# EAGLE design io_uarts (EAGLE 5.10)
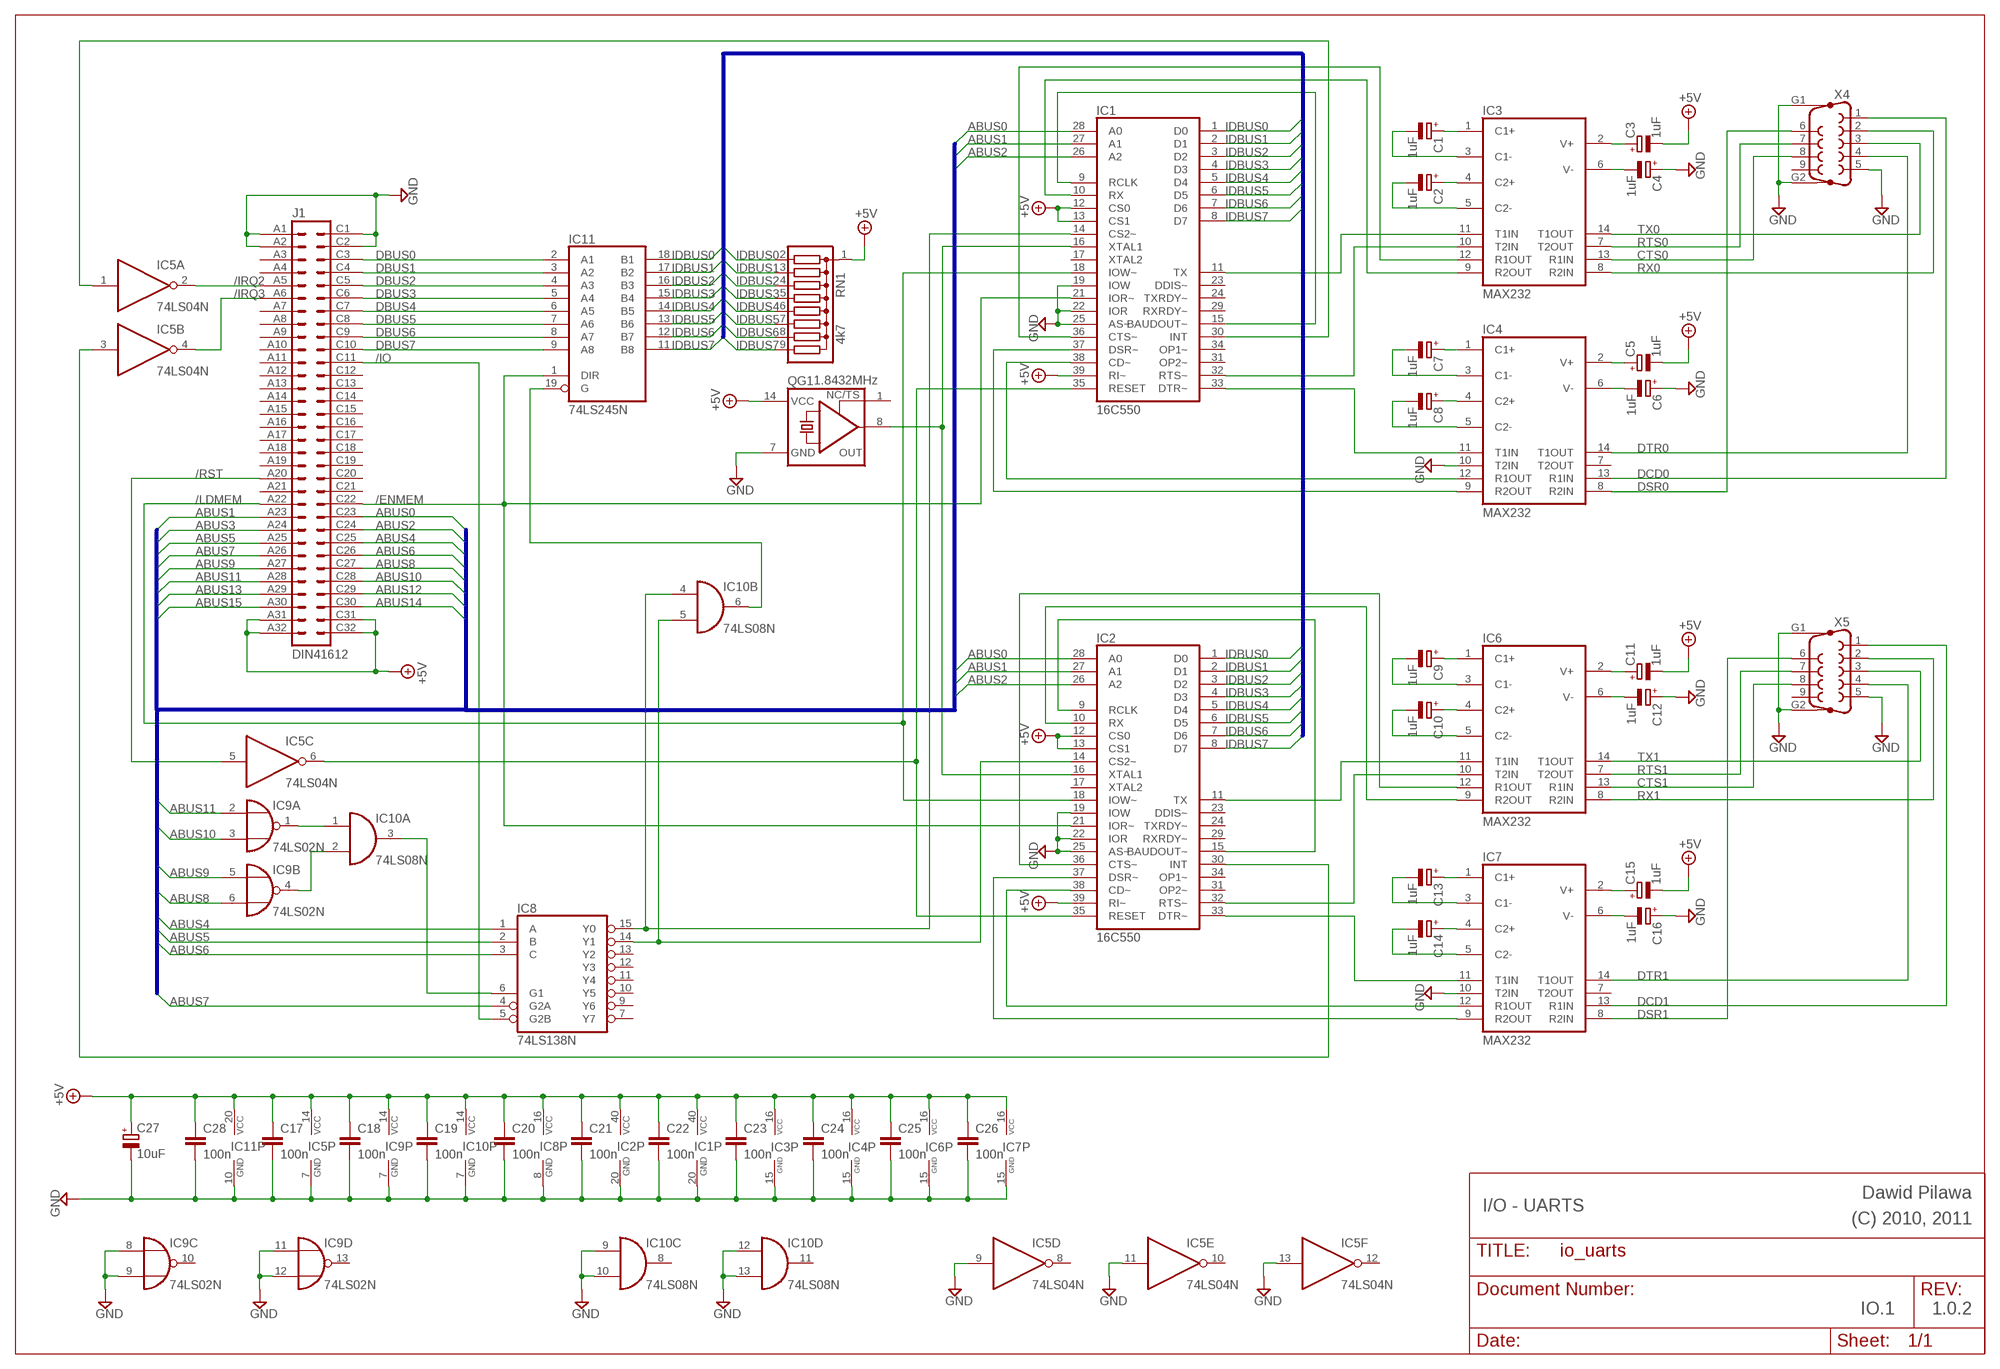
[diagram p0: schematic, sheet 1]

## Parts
C1  1uF  CPOL-EUE5-5  [E5-5]
C2  1uF  CPOL-EUE5-5  [E5-5]
C3  1uF  CPOL-EUE5-5  [E5-5]
C4  1uF  CPOL-EUE5-5  [E5-5]
C5  1uF  CPOL-EUE5-5  [E5-5]
C6  1uF  CPOL-EUE5-5  [E5-5]
C7  1uF  CPOL-EUE5-5  [E5-5]
C8  1uF  CPOL-EUE5-5  [E5-5]
C9  1uF  CPOL-EUE5-5  [E5-5]
C10  1uF  CPOL-EUE5-5  [E5-5]
C11  1uF  CPOL-EUE5-5  [E5-5]
C12  1uF  CPOL-EUE5-5  [E5-5]
C13  1uF  CPOL-EUE5-5  [E5-5]
C14  1uF  CPOL-EUE5-5  [E5-5]
C15  1uF  CPOL-EUE5-5  [E5-5]
C16  1uF  CPOL-EUE5-5  [E5-5]
C17  100n  C-EU050-024X044  [C050-024X044]
C18  100n  C-EU050-024X044  [C050-024X044]
C19  100n  C-EU050-024X044  [C050-024X044]
C20  100n  C-EU050-024X044  [C050-024X044]
C21  100n  C-EU050-024X044  [C050-024X044]
C22  100n  C-EU050-024X044  [C050-024X044]
C23  100n  C-EU050-024X044  [C050-024X044]
C24  100n  C-EU050-024X044  [C050-024X044]
C25  100n  C-EU050-024X044  [C050-024X044]
C26  100n  C-EU050-024X044  [C050-024X044]
C27  10uF  CPOL-EUE5-5  [E5-5]
C28  100n  C-EU050-024X044  [C050-024X044]
IC1  16C550  XR-16C550P  [DIL40]
IC2  16C550  XR-16C550P  [DIL40]
IC3  MAX232  [DIL16]
IC4  MAX232  [DIL16]
IC5  74LS04N  [DIL14]
IC6  MAX232  [DIL16]
IC7  MAX232  [DIL16]
IC8  74LS138N  [DIL16]
IC9  74LS02N  [DIL14]
IC10  74LS08N  [DIL14]
IC11  74LS245N  [DIL20]
J1  DIN41612  VG64B  [VG64B]
QG1  1.8432MHz  XO-14  [DIL14S]
RN1  4k7  G08R  [SIL9]
X4  F09HP  [F09HP]
X5  F09HP  [F09HP]

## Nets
+5V: C3.- C5.- C11.- C15.- C17.1 C18.1 C19.1 C20.1 C21.1 C22.1 C23.1 C24.1 C25.1 C26.1 C27.+ C28.1 IC1.12(CS0) IC1.13(CS1) IC1.39(RI~) IC1.40(VCC) IC2.12(CS0) IC2.13(CS1) IC2.39(RI~) IC2.40(VCC) IC3.16(VCC) IC4.16(VCC) IC5.14(P:VCC) IC6.16(VCC) IC7.16(VCC) IC8.16(VCC) IC9.14(P:VCC) IC10.14(P:VCC) IC11.20(VCC) J1.A31 J1.A32 J1.C31 J1.C32 QG1.14(VCC) RN1.1
/ENMEM: IC1.21(IOR~) IC2.21(IOR~) IC11.1(DIR) J1.C22
/IO: IC8.5(G2B) J1.C11
/IRQ2: IC5.2(A:O) J1.A5
/IRQ3: IC5.4(B:O) J1.A6
/LDMEM: IC1.18(IOW~) IC2.18(IOW~) J1.A22
/RST: IC5.5(C:I) J1.A20
ABUS0: IC1.28(A0) IC2.28(A0) J1.C23
ABUS1: IC1.27(A1) IC2.27(A1) J1.A23
ABUS2: IC1.26(A2) IC2.26(A2) J1.C24
ABUS3: J1.A24
ABUS4: IC8.1(A) J1.C25
ABUS5: IC8.2(B) J1.A25
ABUS6: IC8.3(C) J1.C26
ABUS7: IC8.4(G2A) J1.A26
ABUS8: IC9.6(B:I1) J1.C27
ABUS9: IC9.5(B:I0) J1.A27
ABUS10: IC9.3(A:I1) J1.C28
ABUS11: IC9.2(A:I0) J1.A28
ABUS12: J1.C29
ABUS13: J1.A29
ABUS14: J1.C30
ABUS15: J1.A30
CTS0: IC3.13(R1IN) X4.8
CTS1: IC6.13(R1IN) X5.8
DBUS0: IC11.2(A1) J1.C3
DBUS1: IC11.3(A2) J1.C4
DBUS2: IC11.4(A3) J1.C5
DBUS3: IC11.5(A4) J1.C6
DBUS4: IC11.6(A5) J1.C7
DBUS5: IC11.7(A6) J1.C8
DBUS6: IC11.8(A7) J1.C9
DBUS7: IC11.9(A8) J1.C10
DCD0: IC4.13(R1IN) X4.1
DCD1: IC7.13(R1IN) X5.1
DSR0: IC4.8(R2IN) X4.6
DSR1: IC7.8(R2IN) X5.6
DTR0: IC4.14(T1OUT) X4.4
DTR1: IC7.14(T1OUT) X5.4
GND: C4.+ C6.+ C12.+ C16.+ C17.2 C18.2 C19.2 C20.2 C21.2 C22.2 C23.2 C24.2 C25.2 C26.2 C27.- C28.2 IC1.19(IOW) IC1.20(GND) IC1.22(IOR) IC1.25(AS~) IC2.19(IOW) IC2.20(GND) IC2.22(IOR) IC2.25(AS~) IC3.15(GND) IC4.10(T2IN) IC4.15(GND) IC5.7(P:GND) IC5.9(D:I) IC5.11(E:I) IC5.13(F:I) IC6.15(GND) IC7.10(T2IN) IC7.15(GND) IC8.8(GND) IC9.7(P:GND) IC9.8(C:I0) IC9.9(C:I1) IC9.11(D:I0) IC9.12(D:I1) IC10.7(P:GND) IC10.9(C:I0) IC10.10(C:I1) IC10.12(D:I0) IC10.13(D:I1) IC11.10(GND) J1.A1 J1.A2 J1.C1 J1.C2 QG1.7(GND) X4.5 X4.G1 X4.G2 X5.5 X5.G1 X5.G2
IDBUS0: IC1.1(D0) IC2.1(D0) IC11.18(B1) RN1.2
IDBUS1: IC1.2(D1) IC2.2(D1) IC11.17(B2) RN1.3
IDBUS2: IC1.3(D2) IC2.3(D2) IC11.16(B3) RN1.4
IDBUS3: IC1.4(D3) IC2.4(D3) IC11.15(B4) RN1.5
IDBUS4: IC1.5(D4) IC2.5(D4) IC11.14(B5) RN1.6
IDBUS5: IC1.6(D5) IC2.6(D5) IC11.13(B6) RN1.7
IDBUS6: IC1.7(D6) IC2.7(D6) IC11.12(B7) RN1.8
IDBUS7: IC1.8(D7) IC2.8(D7) IC11.11(B8) RN1.9
N$1: IC1.11(TX) IC3.11(T1IN)
N$2: IC1.10(RX) IC3.9(R2OUT)
N$3: IC10.6(B:O) IC11.19(G)
N$4: IC1.32(RTS~) IC3.10(T2IN)
N$5: IC1.33(DTR~) IC4.11(T1IN)
N$6: IC1.36(CTS~) IC3.12(R1OUT)
N$7: IC1.38(CD~) IC4.12(R1OUT)
N$8: IC1.37(DSR~) IC4.9(R2OUT)
N$9: C1.- IC3.3(C1-)
N$10: C1.+ IC3.1(C1+)
N$11: C2.+ IC3.4(C2+)
N$12: C2.- IC3.5(C2-)
N$13: C4.- IC3.6(V-)
N$14: C3.+ IC3.2(V+)
N$15: IC1.9(RCLK) IC1.15(BAUDOUT~)
N$16: C6.- IC4.6(V-)
N$17: C5.+ IC4.2(V+)
N$18: C7.- IC4.3(C1-)
N$19: C7.+ IC4.1(C1+)
N$20: C8.+ IC4.4(C2+)
N$21: C8.- IC4.5(C2-)
N$22: IC9.1(A:O) IC10.1(A:I0)
N$23: C9.- IC6.3(C1-)
N$24: IC1.30(INT) IC5.1(A:I)
N$25: IC2.30(INT) IC5.3(B:I)
N$26: IC9.4(B:O) IC10.2(A:I1)
N$27: IC8.6(G1) IC10.3(A:O)
N$28: IC1.14(CS2~) IC8.15(Y0) IC10.4(B:I0)
N$29: IC2.14(CS2~) IC8.14(Y1) IC10.5(B:I1)
N$30: IC2.9(RCLK) IC2.15(BAUDOUT~)
N$31: IC2.11(TX) IC6.11(T1IN)
N$32: IC2.32(RTS~) IC6.10(T2IN)
N$33: IC2.33(DTR~) IC7.11(T1IN)
N$34: IC2.38(CD~) IC7.12(R1OUT)
N$35: IC2.37(DSR~) IC7.9(R2OUT)
N$36: IC2.10(RX) IC6.9(R2OUT)
N$37: IC2.36(CTS~) IC6.12(R1OUT)
N$38: C9.+ IC6.1(C1+)
N$39: IC1.35(RESET) IC2.35(RESET) IC5.6(C:O)
N$40: C10.+ IC6.4(C2+)
N$41: C10.- IC6.5(C2-)
N$42: C12.- IC6.6(V-)
N$43: C11.+ IC6.2(V+)
N$44: C13.- IC7.3(C1-)
N$45: C13.+ IC7.1(C1+)
N$46: C14.+ IC7.4(C2+)
N$47: C14.- IC7.5(C2-)
N$48: C16.- IC7.6(V-)
N$49: C15.+ IC7.2(V+)
N$50: IC1.16(XTAL1) IC2.16(XTAL1) QG1.8(OUT)
RTS0: IC3.7(T2OUT) X4.7
RTS1: IC6.7(T2OUT) X5.7
RX0: IC3.8(R2IN) X4.2
RX1: IC6.8(R2IN) X5.2
TX0: IC3.14(T1OUT) X4.3
TX1: IC6.14(T1OUT) X5.3
Unconnected: IC1.17(XTAL2) IC1.23(DDIS~) IC1.24(TXRDY~) IC1.29(RXRDY~) IC1.31(OP2~) IC1.34(OP1~) IC2.17(XTAL2) IC2.23(DDIS~) IC2.24(TXRDY~) IC2.29(RXRDY~) IC2.31(OP2~) IC2.34(OP1~) IC4.7(T2OUT) IC5.8(D:O) IC5.10(E:O) IC5.12(F:O) IC7.7(T2OUT) IC8.7(Y7) IC8.9(Y6) IC8.10(Y5) IC8.11(Y4) IC8.12(Y3) IC8.13(Y2) IC9.10(C:O) IC9.13(D:O) IC10.8(C:O) IC10.11(D:O) J1.A3 J1.A4 J1.A7 J1.A8 J1.A9 J1.A10 J1.A11 J1.A12 J1.A13 J1.A14 J1.A15 J1.A16 J1.A17 J1.A18 J1.A19 J1.A21 J1.C12 J1.C13 J1.C14 J1.C15 J1.C16 J1.C17 J1.C18 J1.C19 J1.C20 J1.C21 QG1.1(TS) X4.9 X5.9

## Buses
ABUS[0..15]
IDBUS[0..7]

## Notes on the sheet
- Dawid Pilawa
- I/O - UARTS | (C) 2010, 2011
- IO.1 | 1.0.2

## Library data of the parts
C1-C16 C27 = rcl:CPOL-EU: POLARIZED CAPACITOR, European symbol
C17-C26 C28 = rcl:C-EU: CAPACITOR, European symbol
IC1 IC2 = exar:XR-16C550P: UART/FIFO
IC3 IC4 IC6 IC7 = maxim:MAX232: RS232 TRANSEIVER
IC5 = 74xx-eu:74*04: Hex INVERTER
IC8 = 74xx-eu:74*138: 3-line to 8-line DECODER/DEMULTIPLEXER
IC9 = 74xx-eu:74*02: Quad 2-input NOR gate
IC10 = 74xx-eu:74*08: Quad 2-input AND gate
IC11 = 74xx-eu:74*245: Octal BUS TRANSCEIVER, 3-state
J1 = 19inch:VG64: PCB EUROCARD, 64-pin type C/AC, 2.54 mm
QG1 = crystal:XO-: CRYSTAL
RN1 = resistor-sil:G08R: SIL RESISTOR
X4 X5 = con-subd:F09HP: SUB-D

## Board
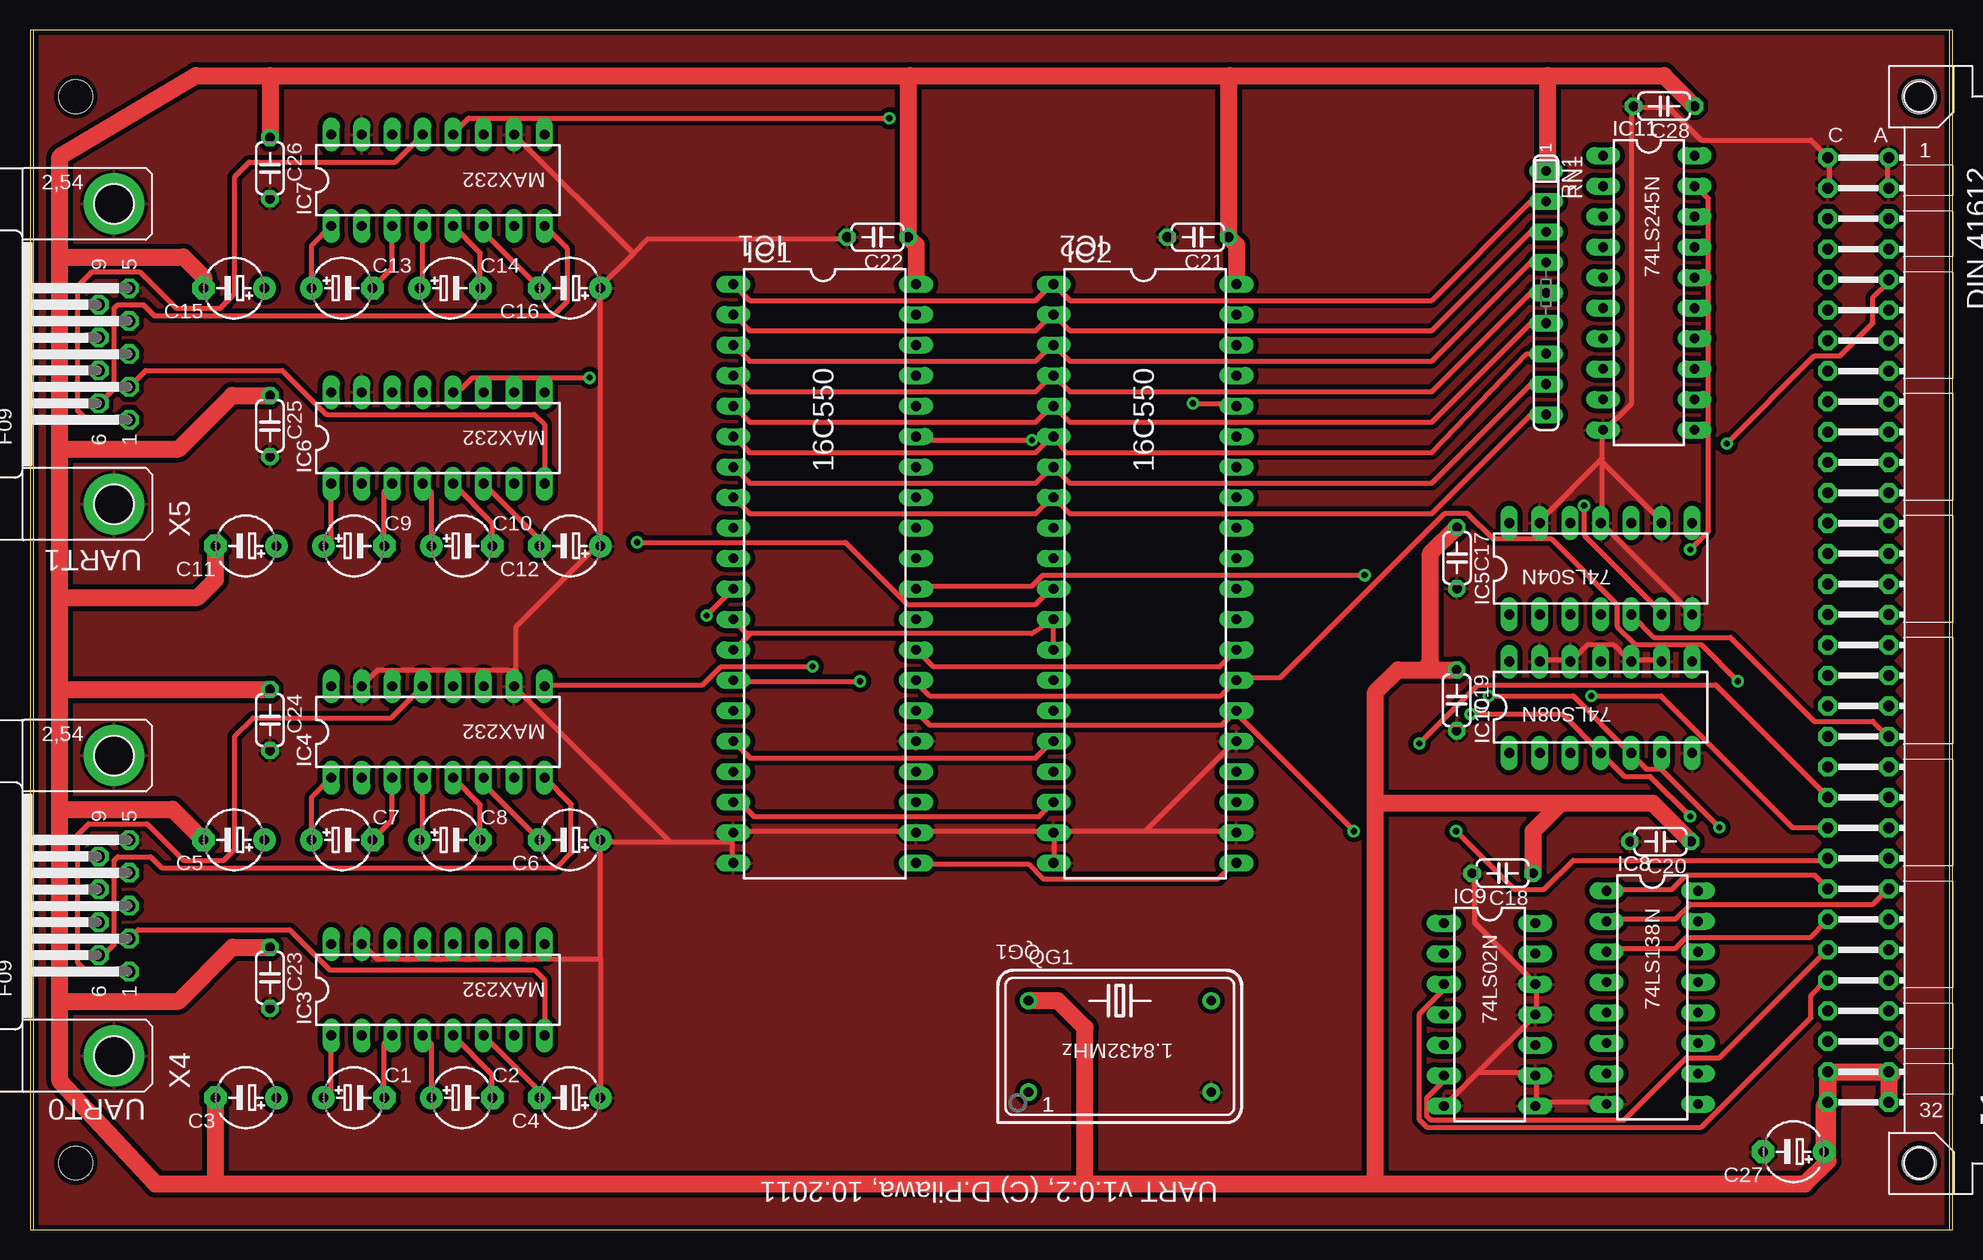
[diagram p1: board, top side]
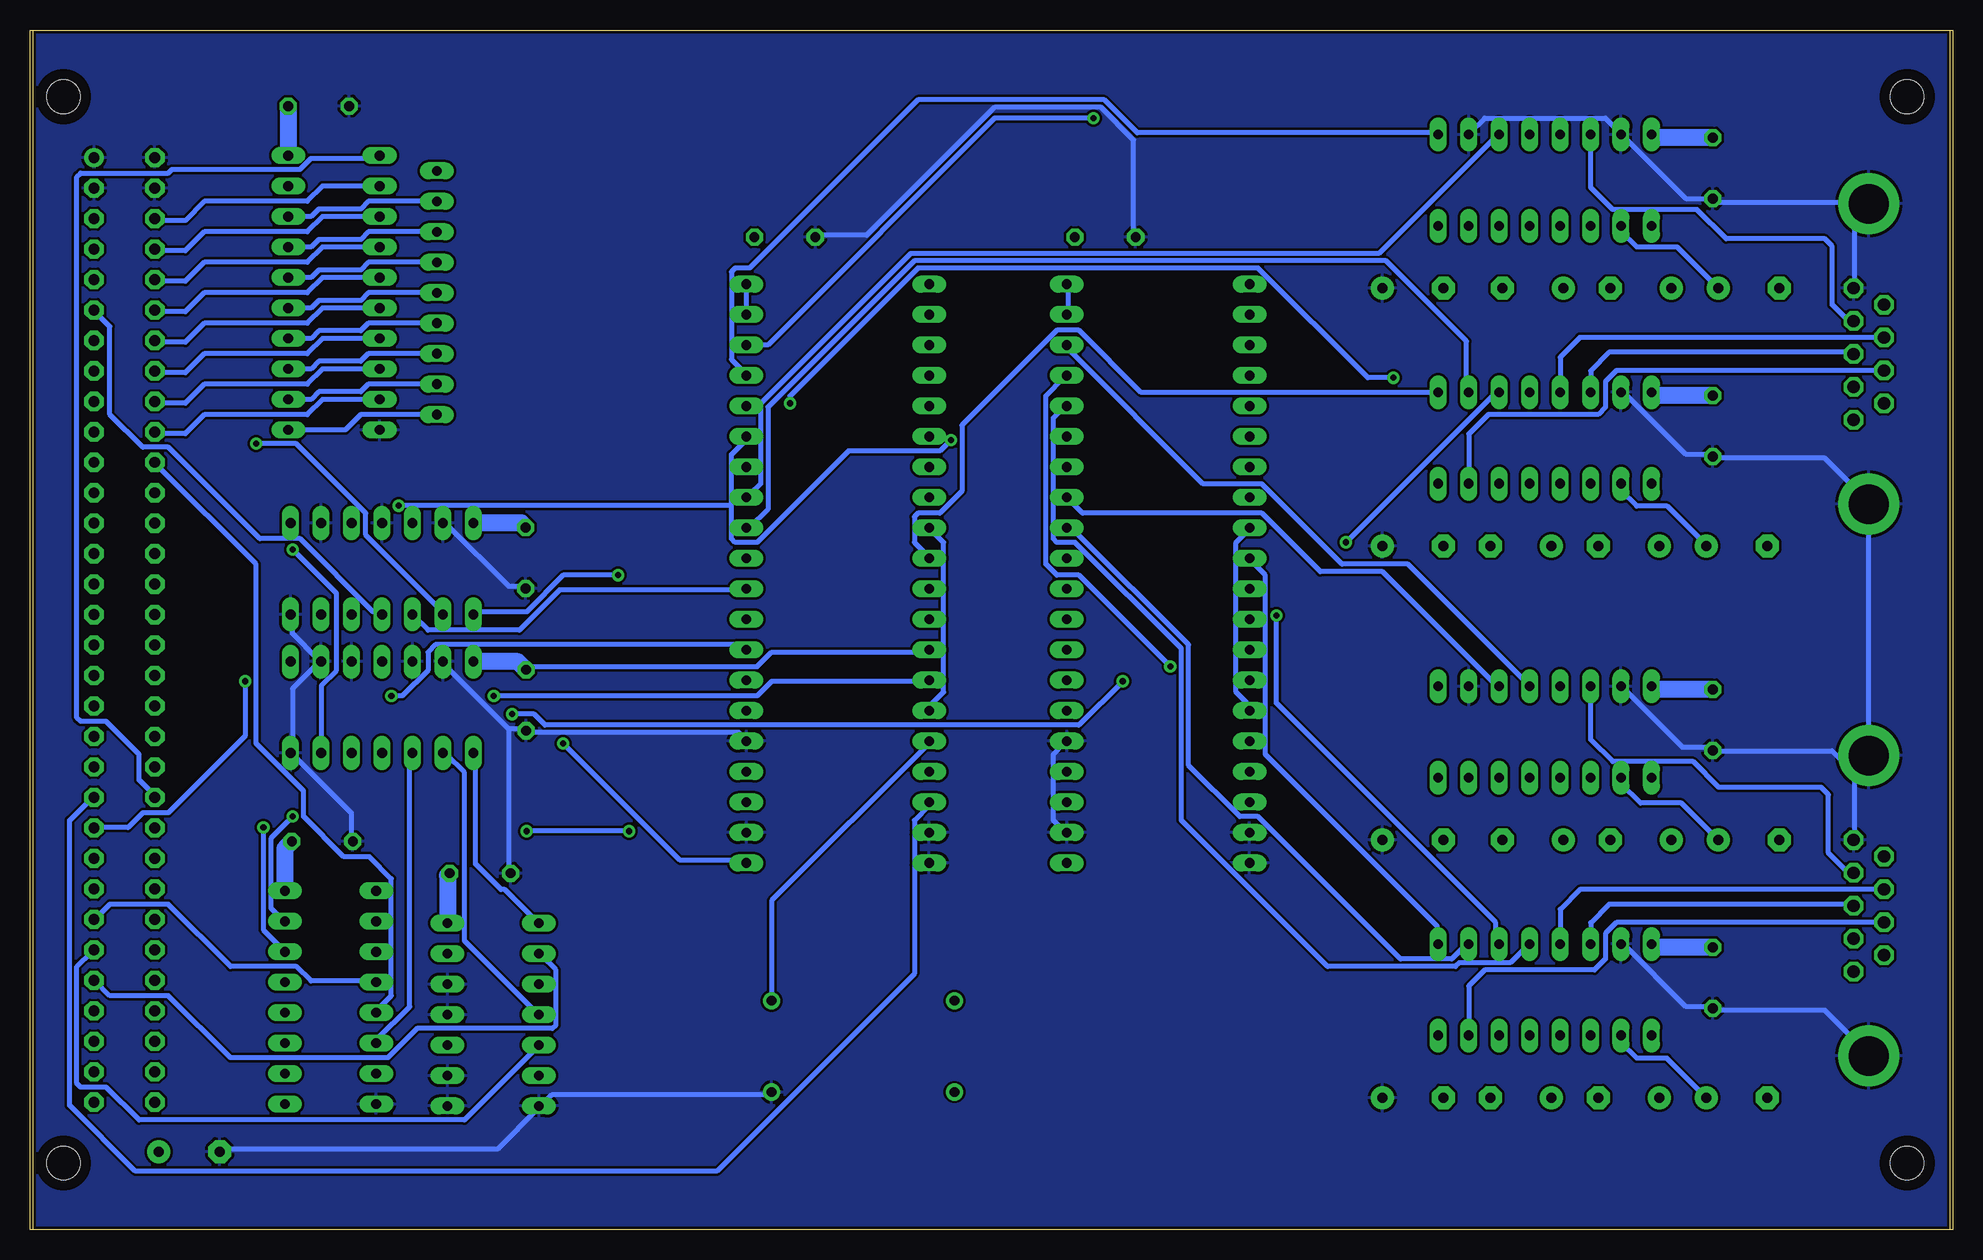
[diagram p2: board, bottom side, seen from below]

Size 160.27 x 100.03 mm. Coordinates in mm from the lower left corner, seen from the top.
Outline: 0,0.01 160,0.01 160,100.01 0,100.01 0,0.01
Copper layers (1*16): Top 0.035mm / dielectric 1.5mm / Bottom 0.035mm
Design rules "SparkFun_squarepads": minimum track width 8mil, minimum drill 20mil, track to track 8mil, track to pad 8mil, pad to pad 8mil, via to via 8mil, smd to smd 8mil, copper to edge 10mil, drill to drill 8mil, minimum pad ring 12mil, minimum via ring 10mil, stop-mask expansion 4mil, vias tented up to drill 25mil, thermal gap 10mil

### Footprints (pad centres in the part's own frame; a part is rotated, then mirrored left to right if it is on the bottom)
E5-5 = drill 0.813 pad 1.905 round: + -2.54,0 | drill 0.813 pad 1.905 octagon: - 2.54,0
C050-024X044 = drill 0.813 octagon: 1 -2.54,0; 2 2.54,0
DIL40 = drill 0.813 long: 1 -24.13,-7.62; 2 -21.59,-7.62; 3 -19.05,-7.62; 4 -16.51,-7.62; 5 -13.97,-7.62; 6 -11.43,-7.62; 7 -8.89,-7.62; 8 -6.35,-7.62; 9 -3.81,-7.62; 10 -1.27,-7.62; 11 1.27,-7.62; 12 3.81,-7.62; 13 6.35,-7.62; 14 8.89,-7.62; 15 11.43,-7.62; 16 13.97,-7.62; 17 16.51,-7.62; 18 19.05,-7.62; 19 21.59,-7.62; 20 24.13,-7.62; 21 24.13,7.62; 22 21.59,7.62; 23 19.05,7.62; 24 16.51,7.62; 25 13.97,7.62; 26 11.43,7.62; 27 8.89,7.62; 28 6.35,7.62; 29 3.81,7.62; 30 1.27,7.62; 31 -1.27,7.62; 32 -3.81,7.62; 33 -6.35,7.62; 34 -8.89,7.62; 35 -11.43,7.62; 36 -13.97,7.62; 37 -16.51,7.62; 38 -19.05,7.62; 39 -21.59,7.62; 40 -24.13,7.62
DIL16 = drill 0.813 long: 1 -8.89,-3.81; 2 -6.35,-3.81; 3 -3.81,-3.81; 4 -1.27,-3.81; 5 1.27,-3.81; 6 3.81,-3.81; 7 6.35,-3.81; 8 8.89,-3.81; 9 8.89,3.81; 10 6.35,3.81; 11 3.81,3.81; 12 1.27,3.81; 13 -1.27,3.81; 14 -3.81,3.81; 15 -6.35,3.81; 16 -8.89,3.81
DIL14 = drill 0.813 long: 1 -7.62,-3.81; 2 -5.08,-3.81; 3 -2.54,-3.81; 4 0,-3.81; 5 2.54,-3.81; 6 5.08,-3.81; 7 7.62,-3.81; 8 7.62,3.81; 9 5.08,3.81; 10 2.54,3.81; 11 0,3.81; 12 -2.54,3.81; 13 -5.08,3.81; 14 -7.62,3.81
DIL20 = drill 0.813 long: 1 -11.43,-3.81; 2 -8.89,-3.81; 3 -6.35,-3.81; 4 -3.81,-3.81; 5 -1.27,-3.81; 6 1.27,-3.81; 7 3.81,-3.81; 8 6.35,-3.81; 9 8.89,-3.81; 10 11.43,-3.81; 11 11.43,3.81; 12 8.89,3.81; 13 6.35,3.81; 14 3.81,3.81; 15 1.27,3.81; 16 -1.27,3.81; 17 -3.81,3.81; 18 -6.35,3.81; 19 -8.89,3.81; 20 -11.43,3.81
VG64B = drill 0.914 pad 1.6 round: A1 154.94,39.37 | drill 0.914 pad 1.6 octagon: A2 154.94,36.83; A3 154.94,34.29; A4 154.94,31.75; A5 154.94,29.21; A6 154.94,26.67; A7 154.94,24.13; A8 154.94,21.59; A9 154.94,19.05; A10 154.94,16.51; A11 154.94,13.97; A12 154.94,11.43; A13 154.94,8.89; A14 154.94,6.35; A15 154.94,3.81; A16 154.94,1.27; A17 154.94,-1.27; A18 154.94,-3.81; A19 154.94,-6.35; A20 154.94,-8.89; A21 154.94,-11.43; A22 154.94,-13.97; A23 154.94,-16.51; A24 154.94,-19.05; A25 154.94,-21.59; A26 154.94,-24.13; A27 154.94,-26.67; A28 154.94,-29.21; A29 154.94,-31.75; A30 154.94,-34.29; A31 154.94,-36.83; A32 154.94,-39.37; C1 149.86,39.37; C2 149.86,36.83; C3 149.86,34.29; C4 149.86,31.75; C5 149.86,29.21; C6 149.86,26.67; C7 149.86,24.13; C8 149.86,21.59; C9 149.86,19.05; C10 149.86,16.51; C11 149.86,13.97; C12 149.86,11.43; C13 149.86,8.89; C14 149.86,6.35; C15 149.86,3.81; C16 149.86,1.27; C17 149.86,-1.27; C18 149.86,-3.81; C19 149.86,-6.35; C20 149.86,-8.89; C21 149.86,-11.43; C22 149.86,-13.97; C23 149.86,-16.51; C24 149.86,-19.05; C25 149.86,-21.59; C26 149.86,-24.13; C27 149.86,-26.67; C28 149.86,-29.21; C29 149.86,-31.75; C30 149.86,-34.29; C31 149.86,-36.83; C32 149.86,-39.37 | hole 2.794: 157.48,44.45; 157.48,-44.45; 3.81,-44.45; 3.81,44.45
DIL14S = drill 0.813 round: 1 -7.62,-3.81; 7 7.62,-3.81; 8 7.62,3.81; 14 -7.62,3.81
SIL9 = drill 0.813 long: 1 -10.16,0; 2 -7.62,0; 3 -5.08,0; 4 -2.54,0; 5 0,0; 6 2.54,0; 7 5.08,0; 8 7.62,0; 9 10.16,0
F09HP = drill 1.016 octagon: 1 -5.486,-1.27; 2 -2.743,-1.27; 3 0,-1.27; 4 2.743,-1.27; 5 5.486,-1.27; 6 -4.115,1.27; 7 -1.372,1.27; 8 1.372,1.27; 9 4.115,1.27 | drill 3.302 pad 5.08 round: G1 -12.522,0; G2 12.522,0

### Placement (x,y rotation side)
C1  27,11.01 0 top
C2  36,11.01 0 top
C3  18,11.01 180 top
C4  45,11.01 180 top
C5  17,32.51 180 top
C6  45,32.51 180 top
C7  26,32.51 0 top
C8  35,32.51 0 top
C9  27,57.01 0 top
C10  36,57.01 0 top
C11  18,57.01 180 top
C12  45,57.01 180 top
C13  26,78.51 0 top
C14  35,78.51 0 top
C15  17,78.5 180 top
C16  45,78.51 180 top
C17  118.95,56.01 270 top
C18  122.75,29.73 180 top
C19  118.92,44.15 270 top
C20  135.91,32.37 180 top
C21  97.36,82.76 180 top
C22  70.65,82.76 180 top
C23  20,21.01 270 top
C24  20,42.51 270 top
C25  20,67.01 270 top
C26  20,88.51 270 top
C27  147,6.51 180 top
C28  136.21,93.68 180 top
IC1  66.23,54.71 270 top
IC2  92.94,54.71 270 top
IC3  34,20.01 0 top
IC4  34,41.51 0 top
IC5  130.93,55.11 0 top
IC6  34,66.01 0 top
IC7  34,87.51 0 top
IC8  135.22,19.37 270 top
IC9  121.67,17.94 270 top
IC10  130.93,43.57 0 top
IC11  134.94,78.12 270 top
J1  0,50.01 0 top
QG1  90.84,15.29 0 top
RN1  126.36,78.12 270 top
X4  7,27.01 90 top
X5  7,73.01 90 top

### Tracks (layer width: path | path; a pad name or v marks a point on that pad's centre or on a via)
+5V
  Top 0.406: IC1.12 58.62,50.82 59.74,49.69 60.05,49.69 | 60.05,49.69 83.51,49.69 83.72,49.84 IC2.12 IC2.13 | 60.05,49.69 58.83,48.48 IC1.13
  Top 1.422: J1.C31 J1.C32 149.54,10.32 C27.+ | J1.C31 J1.A31 155.09,13.03 155.26,13.03 154.94,12.71 J1.A32 | J1.C31 149.86,5.73 147.96,3.82 112.47,3.82 | 15.56,3.82 10.48,3.82 2.49,12.42 2.49,18.91 | 15.56,3.82 88.27,3.82 | 88.27,3.82 112.47,3.82 | 20,96.22 13.83,96.22 2.62,89.55 | 20,96.22 73.34,96.22 | 73.34,96.22 100.01,96.22 | 100.01,96.22 126.49,96.22 | 126.49,96.22 136.21,96.22 C28.1 | C18.1 125.29,33.22 127.64,35.57 | 127.64,35.57 135.24,35.57 C20.1 | 100.01,96.22 99.89,96.1 C21.1 100.56,82.09 IC2.40 | 73.34,96.22 73.19,96.06 C22.1 73.86,82.09 IC1.40 | QG1.14 85.69,19.1 87.95,16.84 87.95,4.14 88.27,3.82 | C26.1 20,96.21 20,96.22 | C3.- 15.46,3.92 15.56,3.82 | C11.- 15.46,54.21 13.97,52.72 2.49,52.72 | 14.46,78.58 C15.- 14.46,79.43 12.8,81.09 2.79,81.09 2.49,80.78 | C25.1 16.84,69.55 12.38,65.1 2.49,65.1 | C23.1 16.87,23.55 12.38,19.06 2.64,19.06 2.49,18.91 | 14.46,32.54 C5.- 14.45,32.5 11.89,35.06 2.79,35.06 2.49,34.76 | C17.1 118.89,58.55 116.74,56.4 116.74,47.3 116.13,46.69 | 2.62,89.55 2.49,89.45 | 2.49,18.91 2.49,34.76 | 2.49,34.76 2.49,45.12 | 2.49,45.12 2.49,52.72 | 2.49,65.1 2.49,80.78 | 2.49,80.78 2.49,89.42 2.62,89.55 | C24.1 2.57,45.04 2.49,45.12 | 2.49,52.72 2.49,65.1 | RN1.1 126.49,88.28 126.49,96.22 | 116.13,46.69 114.04,46.69 112.17,44.82 112.17,35.98 | 116.13,46.69 C19.1 | 112.17,35.98 112.17,4.13 112.47,3.82 | 127.64,35.57 112.57,35.57 112.17,35.98
  Bottom 0.406: IC1.39 73.76,76.52 73.76,78.65 IC1.40 | IC2.39 100.58,76.52 100.58,78.65 IC2.40 | IC2.13 85.34,48.17 98.45,48.17 99.67,46.95 118.26,46.95 C19.1
  Bottom 1.422: C19.1 119.61,47.38 IC10.14 | IC9.14 125.47,29.54 C18.1 | IC8.16 139.03,31.78 C20.1 | C28.1 IC11.20 | C26.1 24.84,91.04 IC7.16 | C25.1 24.84,69.55 IC6.16 | C24.1 24.84,45.04 IC4.16 | C23.1 24.84,23.55 IC3.16 | IC5.14 119.32,58.92 C17.1
/ENMEM  (via drill 0.51)
  Top 0.406: IC1.21 74.07,30.49 83.21,30.49 84.43,29.27 99.06,29.27 100.28,30.49 IC2.21 | v115.82,40.55 120.7,45.43 140.51,45.43 149.66,36.28 J1.C22
  Bottom 0.406: IC11.1 131.37,89.32 136.85,89.32 137.77,88.4 148.44,88.4 148.74,88.1 156.06,88.1 156.36,87.79 156.36,42.68 156.06,42.38 153.92,42.38 151.18,39.64 151.18,37.5 149.96,36.28 J1.C22 | v115.82,40.55 106.07,30.8 100.58,30.8 IC2.21
/IO
  Bottom 0.406: IC8.5 131.37,18.3 130.15,19.52 130.15,29.27 131.98,31.1 134.11,31.1 137.47,34.45 137.47,36.59 141.43,40.55 141.43,55.49 149.66,63.72 J1.C11
/IRQ2  (via drill 0.51)
  Top 0.406: v141.43,65.54 148.74,72.86 150.88,72.86 153.62,75.6 153.62,77.74 154.84,78.96 J1.A5
  Bottom 0.406: v141.43,65.54 138.07,65.54 132.28,59.75 132.28,57.92 125.88,51.52 IC5.2
/IRQ3
  Bottom 0.406: IC5.4 131.06,51.52 131.67,51.52 137.77,57.62 141.12,57.62 148.74,65.24 150.88,65.24 153.62,67.98 153.62,75.3 154.84,76.52 J1.A6
/LDMEM
  Top 0.406: IC1.18 59.15,35.66 60.35,34.45 84.12,34.45 IC2.18
  Bottom 0.406: J1.A22 155.14,35.98 156.97,34.15 156.97,10.38 151.49,4.89 103.02,4.89 86.56,21.35 86.56,34.15 85.34,35.37 IC2.18
/RST
  Top 0.406: IC5.5 133.5,51.22 135.33,49.39 141.73,49.39 148.74,42.38 153.62,42.38 154.84,41.16 J1.A20
ABUS0  (via drill 0.51)
  Top 0.406: IC1.28 73.88,48.36 75.29,46.95 99.16,46.95 IC2.28 | v130.15,44.51 135.94,44.51 146.91,33.54 149.66,33.54 J1.C23
  Bottom 0.406: v130.15,44.51 129.24,44.51 127.1,46.65 127.1,48.17 126.49,48.78 100.89,48.78 100.58,48.48 IC2.28
ABUS1  (via drill 0.51)
  Top 0.406: IC1.27 73.86,45.64 74.98,44.51 99.26,44.51 IC2.27 100.58,46.04 104.24,46.04 117.96,59.75 119.79,59.75 121.92,57.62 126.8,57.62 132.28,52.13 132.28,50.3 133.81,48.78 139.29,48.78 v142.34,45.73
  Bottom 0.406: v142.34,45.73 142.34,41.16 148.74,34.76 150.88,34.76 152.09,33.54 154.84,33.54 J1.A23
ABUS2  (via drill 0.51)
  Top 0.406: IC1.26 73.86,43.2 74.98,42.07 99.36,42.07 IC2.26 100.58,42.99 v110.34,33.24 | v118.87,33.24 123.75,28.36 126.19,28.36 128.63,30.8 149.66,30.8 J1.C24
  Bottom 0.406: v110.34,33.24 v118.87,33.24
ABUS4
  Top 0.406: IC8.1 131.67,28.36 136.85,28.36 138.07,29.58 148.74,29.58 149.66,28.66 J1.C25
ABUS5
  Top 0.406: IC8.2 131.67,25.92 137.16,25.92 138.38,27.14 153.62,27.14 154.84,28.36 J1.A25
ABUS6
  Top 0.406: IC8.3 131.67,23.48 137.16,23.48 138.07,24.4 148.44,24.4 149.66,25.62 J1.C26
ABUS7
  Bottom 0.406: IC8.4 131.67,20.74 136.85,20.74 138.07,21.96 143.56,21.96 148.74,27.14 153.62,27.14 154.84,25.92 J1.A26
ABUS8
  Top 0.406: IC9.6 117.65,12.81 117.65,12.2 116.43,10.99 116.43,9.46 116.74,9.16 132.89,9.16 138.07,14.34 140.82,14.34 149.66,23.18 J1.C27
ABUS9
  Bottom 0.406: IC9.5 117.96,15.25 124.05,9.16 151.18,9.16 153.92,11.9 156.06,11.9 156.36,12.2 156.36,21.96 155.14,23.18 J1.A27
ABUS10
  Top 0.406: IC9.3 117.65,20.43 117.65,19.82 115.82,18 115.82,9.16 116.43,8.55 139.29,8.55 148.44,17.69 148.44,19.52 149.66,20.74 J1.C28
ABUS11
  Bottom 0.406: IC9.2 117.65,22.87 116.43,21.65 116.43,17.08 116.74,16.78 128.02,16.78 130.45,14.34 143.56,14.34 148.74,19.52 153.62,19.52 154.84,20.74 J1.A28
CTS0
  Bottom 0.406: IC3.13 32.73,26.72 31.09,28.36 5.75,28.36 X4.8
CTS1
  Bottom 0.406: IC6.13 32.73,72.74 31.09,74.38 X5.8
DBUS0
  Bottom 0.406: IC11.2 135.89,87.01 137.16,85.74 145.73,85.74 147.32,84.15 149.86,84.15 J1.C3
DBUS1
  Bottom 0.406: IC11.3 135.89,84.47 137.16,83.2 145.73,83.2 147.32,81.61 149.86,81.61 J1.C4
DBUS2
  Bottom 0.406: IC11.4 135.89,81.93 137.16,80.66 145.73,80.66 147.32,79.07 149.86,79.07 J1.C5
DBUS3
  Bottom 0.406: IC11.5 135.89,79.39 137.16,78.12 145.73,78.12 147.32,76.53 149.86,76.53 J1.C6
DBUS4
  Bottom 0.406: IC11.6 135.89,76.85 137.16,75.58 145.73,75.58 147.32,73.99 149.86,73.99 J1.C7
DBUS5
  Bottom 0.406: IC11.7 135.89,74.31 137.16,73.04 145.73,73.04 147.32,71.45 149.86,71.45 J1.C8
DBUS6
  Bottom 0.406: IC11.8 135.89,71.77 137.16,70.5 145.73,70.5 147.32,68.91 149.86,68.91 J1.C9
DBUS7
  Bottom 0.406: IC11.9 135.89,69.23 137.16,67.96 145.73,67.96 147.32,66.37 149.86,66.37 J1.C10
DCD0
  Top 0.406: X4.1 4.7,21.53 3.96,22.26 3.96,32.93 4.88,33.85 9.75,33.85 12.8,30.8 16.15,30.8 17.07,31.71 17.07,41.16 18.59,42.68 30.1,42.68 IC4.13
DCD1
  Top 0.406: X5.1 4.72,67.53 3.96,68.29 3.96,78.65 5.18,79.87 9.14,79.87 12.19,76.82 15.85,76.82 17.07,78.04 17.07,87.79 18.29,89.01 30.43,89.01 IC7.13
DSR0
  Top 0.406: X4.6 6.12,22.9 7.01,23.79 7.01,30.8 7.32,31.1 10.06,31.1 10.97,30.19 43.89,30.19 45.11,31.41 45.11,35.47 IC4.8
DSR1
  Top 0.406: X5.6 5.79,68.9 7.01,70.12 7.01,76.82 7.32,77.13 9.45,77.13 10.36,76.21 43.59,76.21 44.81,77.43 44.81,81.78 IC7.8
DTR0
  Bottom 0.406: X4.4 8.71,29.76 10.36,31.41 10.36,36.28 10.97,36.89 19.51,36.89 21.64,39.03 28.35,39.03 30.18,40.86 30.18,45.3 IC4.14
DTR1
  Bottom 0.406: X5.4 8.69,75.76 10.06,77.13 10.06,82 10.67,82.61 18.9,82.61 21.34,85.05 28.35,85.05 30.18,86.88 30.18,91.3 IC7.14
GND
  Top 0.406: 125.58,10.68 125.58,12.81 IC9.9 125.27,13.12 120.7,13.12 | 125.58,10.68 125.58,10.38 IC9.8 125.58,10.68 | 125.58,10.68 131.37,10.68 IC8.8 | 120.7,13.12 117.96,10.38 IC9.7 | 120.7,13.12 125.27,17.69 IC9.11 125.58,18 125.58,20.43 IC9.12 125.27,20.74 120.4,25.62 120.4,29.58 C18.2 | 154.84,86.88 154.84,89.32 J1.A1 | 149.96,86.88 149.96,89.32 J1.C1 149.66,89.62 148.44,90.84 139.29,90.84 136.55,93.59 133.81,93.59 C28.2 133.5,93.59 133.5,68.9 131.37,66.76 IC11.10 131.06,66.46 131.06,64.33 | 149.96,86.88 154.84,86.88 | 154.84,86.88 J1.A2 | 149.96,86.88 J1.C2 | IC10.13 125.88,47.56 128.32,47.56 IC10.12 128.63,47.56 129.84,48.78 131.98,48.78 133.2,47.56 IC10.10 133.5,47.56 135.94,47.56 IC10.9 | 131.06,64.02 131.06,64.33 | 131.06,64.02 131.06,59.14 IC5.11 131.06,58.84 138.38,51.52 IC5.7 | 131.06,64.02 135.94,59.14 IC5.9 | 131.06,64.33 125.88,59.14 IC5.13 | 50.29,81.39 47.55,78.65 C16.+ 47.55,78.35 47.55,57.31 C12.+ 47.24,57.01 40.54,50.3 40.54,46.65 | 50.29,81.39 51.51,82.61 67.97,82.61 C22.2 | 50.29,81.39 40.54,91.15 IC7.10 | 40.54,46.65 40.54,45.43 IC4.10 40.54,45.12 53.34,32.32 | 40.54,46.65 28.96,46.65 27.74,45.43 IC4.15 | 58.52,32.32 58.52,32.93 IC1.19 58.83,33.24 73.76,33.24 IC1.22 74.07,33.24 85.04,33.24 IC2.19 | 58.52,32.32 58.52,30.8 IC1.20 | 47.55,32.32 53.34,32.32 | 53.34,32.32 58.52,32.32 | 47.55,22.57 47.55,32.32 | 47.55,22.57 47.55,11.29 C4.+ | 47.55,32.32 C6.+ | IC2.20 85.34,30.8 85.34,32.93 IC2.19 | 92.96,33.24 85.34,33.24 IC2.19 | 92.96,33.24 100.28,33.24 IC2.22 | 92.96,33.24 100.28,40.55 IC2.25 | 47.55,22.57 28.96,22.57 27.74,23.79 IC3.15
  Bottom 0.406: QG1.7 98.75,11.29 116.74,11.29 117.65,10.38 IC9.7 117.96,10.07 121.31,6.72 144.17,6.72 C27.- | 120.4,41.77 119.18,41.77 C19.2 118.87,41.47 101.19,41.47 100.58,40.86 IC2.25 | 120.4,41.77 125.88,47.26 IC10.13 | 120.4,41.77 120.4,29.88 C18.2 | C20.2 133.5,32.63 133.5,34.76 138.38,39.64 IC10.7 138.38,39.94 138.38,45.12 136.25,47.26 IC10.9 136.25,47.56 138.38,49.69 138.38,51.22 IC5.7 | C17.2 119.18,53.66 120.4,53.66 125.58,58.84 IC5.13 | 8.23,85.66 7.01,85.66 X5.G2 8.23,85.66 | 8.23,85.66 19.81,85.66 C26.2 20.12,85.97 22.25,85.97 27.43,91.15 IC7.15 27.74,91.45 28.96,92.67 39.01,92.67 40.23,91.45 IC7.10 | 8.23,85.66 8.23,78.65 X5.5 | C21.2 94.79,82.92 90.53,82.92 79.86,93.59 71.02,93.59 68.28,90.84 68.28,82.92 C22.2 | IC6.15 27.43,69.81 22.25,64.63 20.12,64.63 C25.2 19.81,64.33 10.67,64.33 7.01,60.67 X5.G1 7.01,60.36 7.01,39.64 X4.G2 | IC4.15 27.43,45.12 22.55,40.25 20.12,40.25 C24.2 19.81,39.94 10.06,39.94 8.23,38.11 | 8.23,38.11 8.23,32.63 X4.5 | 8.23,38.11 7.01,39.33 X4.G2 | 8.23,38.11 X4.G2 | IC3.15 27.43,23.79 22.25,18.61 20.12,18.61 C23.2 19.81,18.3 10.67,18.3 7.01,14.64 X4.G1 | IC1.25 74.07,40.55 74.98,39.64 74.98,34.15 74.07,33.24 IC1.22
  pour Top (isolate 0.406): 0,99.99 160.32,99.99 160.32,0.01 0,0.01
  pour Bottom: 0,99.99 160.32,99.99 160.32,0.01 0,0.01
IDBUS0
  Top 0.406: IC1.1 59.97,77.48 83.82,77.48 85.17,78.84 IC2.1 86.68,77.48 116.84,77.48 125.09,85.74 RN1.2
  Bottom 0.406: IC11.18 136.84,84.47 136.21,85.1 132.7,85.1 132.07,85.74 RN1.2
IDBUS1
  Top 0.406: IC1.2 59.97,74.94 83.82,74.94 85.17,76.3 IC2.2 86.68,74.94 116.84,74.94 125.09,83.2 RN1.3
  Bottom 0.406: IC11.17 136.84,81.93 136.21,82.56 132.7,82.56 132.07,83.2 RN1.3
IDBUS2
  Top 0.406: IC1.3 59.97,72.4 83.82,72.4 85.17,73.76 IC2.3 86.68,72.4 116.84,72.4 125.09,80.66 RN1.4
  Bottom 0.406: IC11.16 136.84,79.39 136.21,80.02 132.7,80.02 132.07,80.66 RN1.4
IDBUS3
  Top 0.406: IC1.4 59.97,69.86 83.82,69.86 85.17,71.22 IC2.4 86.68,69.86 116.84,69.86 125.09,78.12 RN1.5
  Bottom 0.406: IC11.15 136.84,76.85 136.21,77.48 132.7,77.48 132.07,78.12 RN1.5
IDBUS4
  Top 0.406: IC1.5 59.97,67.32 83.82,67.32 85.17,68.68 IC2.5 86.68,67.32 116.84,67.32 125.09,75.58 RN1.6
  Bottom 0.406: IC11.14 136.84,74.31 136.21,74.94 132.7,74.94 132.07,75.58 RN1.6
IDBUS5
  Top 0.406: IC1.6 59.97,64.78 83.82,64.78 85.17,66.14 IC2.6 86.36,64.78 116.84,64.78 124.78,73.04 RN1.7
  Bottom 0.406: IC11.13 136.84,71.77 136.21,72.4 132.7,72.4 132.07,73.04 RN1.7
IDBUS6
  Top 0.406: IC1.7 59.97,62.24 83.82,62.24 85.17,63.6 IC2.7 86.68,62.24 116.84,62.24 125.09,70.5 RN1.8
  Bottom 0.406: IC11.12 136.84,69.23 136.21,69.86 132.7,69.86 132.07,70.5 RN1.8
IDBUS7
  Top 0.406: IC1.8 59.97,59.7 83.82,59.7 85.17,61.06 IC2.8 86.68,59.7 116.84,59.7 125.09,67.96 RN1.9
  Bottom 0.406: IC11.11 133.99,66.69 132.72,67.96 RN1.9
N$1  (via drill 0.51)
  Top 0.406: v56.39,51.22 58.52,53.35 IC1.11
  Bottom 0.406: v56.39,51.22 56.39,43.9 38.1,25.62 38.1,24.09 IC3.11
N$2
  Bottom 0.406: IC3.9 42.98,24.09 42.98,25.31 57.3,39.64 57.3,54.57 58.52,55.79 IC1.10
N$3  (via drill 0.51)
  Top 0.406: v138.38,56.71 139.9,58.23 139.9,85.97 138.99,86.88 IC11.19
  Bottom 0.406: v138.38,56.71 134.72,53.05 134.72,46.65 135.94,45.43 135.94,39.94 IC10.6
N$4
  Bottom 0.406: IC3.10 40.54,23.79 41.76,22.57 46.02,22.57 57.91,34.45 59.44,34.45 63.7,38.72 63.7,48.78 73.15,58.23 73.76,58.23 IC1.32
N$5
  Bottom 0.406: IC4.11 38.1,45.43 47.55,54.88 52.73,54.88 57.61,59.75 72.54,59.75 73.76,60.97 IC1.33
N$6
  Bottom 0.406: IC3.12 35.36,23.79 36.88,22.26 41.15,22.26 41.45,21.96 52.12,21.96 64.31,34.15 64.31,48.48 73.15,57.31 74.68,57.31 74.98,57.62 74.98,67.68 74.07,68.59 IC1.36
N$7
  Bottom 0.406: IC4.12 35.36,45.43 45.41,55.49 50.9,55.49 57.61,62.19 62.48,62.19 73.76,73.47 IC1.38
N$8  (via drill 0.51)
  Top 0.406: v65.23,46.95 57.61,46.95 56.08,45.43 42.98,45.43 IC4.9
  Bottom 0.406: v65.23,46.95 72.85,54.57 74.68,54.57 75.59,55.49 75.59,69.51 74.07,71.03 IC1.37
N$9
  Top 0.406: C1.- 29.54,15.55 IC3.3
N$10
  Top 0.406: C1.+ 25.11,11.66 IC3.1
N$11
  Top 0.406: C2.+ 33.46,15.47 IC3.4
N$12
  Top 0.406: C2.- 38.54,12.93 IC3.5
N$13
  Top 0.406: C4.- 42.46,11.55 IC3.6
N$14
  Bottom 0.406: C3.+ 23.83,14.3 26.35,14.3 27.65,15.6 IC3.2
N$15
  Bottom 0.406: IC1.15 58.83,43.29 58.83,43.9 59.74,44.82 59.74,57.31 58.83,58.23 IC1.9
N$16
  Top 0.406: C6.- 37.81,37.15 IC4.6
N$17
  Bottom 0.406: C5.+ 22.61,35.57 26.04,35.57 27.65,37.19 IC4.2
N$18
  Top 0.406: C7.- 30.19,34.15 IC4.3
N$19
  Top 0.406: C7.+ 23.46,36.04 IC4.1
N$20
  Top 0.406: C8.+ 32.73,32.78 IC4.4
N$21
  Top 0.406: IC4.5 37.54,35.43 C8.-
N$22
  Bottom 0.406: IC9.1 117.96,25.62 120.7,28.36 121.01,28.36 123.14,30.49 123.14,39.64 IC10.1
N$23
  Top 0.406: IC6.3 29.54,61.55 C9.-
N$24  (via drill 0.51)
  Top 0.406: v111.25,54.57 84.43,54.57 83.52,53.66 74.07,53.66 IC1.30
  Bottom 0.406: v111.25,54.57 115.82,54.57 118.87,51.52 123.14,51.52 IC5.1
N$25
  Bottom 0.406: IC2.30 100.58,53.35 116.13,53.35 119.48,50 127.1,50 128.32,51.22 IC5.3
N$26
  Bottom 0.406: IC9.4 117.96,18 124.05,24.09 124.05,38.11 125.58,39.64 IC10.2
N$27
  Bottom 0.406: IC8.6 131.37,15.86 128.63,18.61 128.63,39.64 IC10.3
N$28  (via drill 0.51)
  Top 0.406: v69.19,45.73 58.83,45.73 IC1.14 | v120.09,42.99 127.71,42.99 130.76,39.94 IC10.4 131.06,39.64 132.89,37.81 135.03,37.81 v138.38,34.45
  Bottom 0.406: v69.19,45.73 72.85,42.07 117.35,42.07 118.26,42.99 v120.09,42.99 | v138.38,34.45 140.21,32.63 140.21,26.83 139.29,25.92 IC8.15
N$29  (via drill 0.51)
  Top 0.406: v121.61,44.51 128.63,44.51 133.2,39.94 IC10.5 133.5,39.64 134.72,38.42 135.94,38.42 v140.82,33.54
  Bottom 0.406: v121.61,44.51 99.67,44.51 98.45,45.73 85.34,45.73 IC2.14 | v140.82,33.54 140.82,25.01 139.29,23.48 IC8.14
N$30
  Bottom 0.406: IC2.15 85.04,43.29 85.04,43.9 84.12,44.82 84.12,57.31 85.04,58.23 IC2.9
N$31  (via drill 0.51)
  Top 0.406: v50.6,57.31 67.97,57.31 73.15,52.13 83.82,52.13 85.04,53.35 IC2.11
  Bottom 0.406: v50.6,57.31 38.1,69.81 IC6.11
N$32
  Bottom 0.406: IC6.10 40.54,70.12 40.54,74.08 47.24,80.78 86.56,80.78 98.75,68.59 98.75,60.06 100.28,58.53 IC2.32
N$33
  Bottom 0.406: IC7.11 38.1,91.15 47.85,81.39 86.87,81.39 99.36,68.9 99.36,62.19 100.28,61.28 IC2.33
N$34  (via drill 0.51)
  Top 0.406: v71.63,92.67 36.58,92.67 35.36,91.45 IC7.12
  Bottom 0.406: v71.63,92.67 79.86,92.67 98.75,73.77 100.28,73.77 IC2.38
N$35
  Bottom 0.406: IC7.9 42.98,91.45 67.97,91.45 70.71,94.2 86.26,94.2 100.28,80.17 101.5,80.17 101.8,79.87 101.8,72.55 100.58,71.34 IC2.37
N$36
  Bottom 0.406: IC6.9 42.98,69.81 67.67,69.81 72.85,74.99 74.68,74.99 82.6,67.07 82.6,61.58 84.43,59.75 86.26,59.75 86.56,59.45 86.56,57.31 85.34,56.1 IC2.10
N$37  (via drill 0.51)
  Top 0.406: v46.63,71.03 36.88,71.03 35.97,70.12 35.36,70.12 IC6.12 | v96.93,68.9 100.28,68.9 IC2.36
  Bottom 0.406: v46.63,71.03 48.77,71.03 57.91,80.17 86.26,80.17 96.93,69.51 v96.93,68.9
N$38
  Top 0.406: C9.+ 25.11,57.66 IC6.1
N$39  (via drill 0.51)
  Top 0.406: v83.52,65.85 74.07,65.85 IC1.35 | v129.54,60.36 129.54,57.92 135.94,51.52 IC5.6
  Bottom 0.406: v83.52,65.85 84.43,64.93 92.05,64.93 99.67,57.31 101.5,57.31 101.8,57.62 101.8,60.36 | 101.8,60.36 101.8,64.63 100.58,65.85 IC2.35 | 101.8,60.36 v129.54,60.36
N$40
  Top 0.406: IC6.4 33.46,61.47 C10.+
N$41
  Top 0.406: IC6.5 38.54,58.93 C10.-
N$42
  Top 0.406: IC6.6 42.46,57.55 C12.-
N$43
  Bottom 0.406: C11.+ 20.64,57.11 20.64,57.16 23.81,60.34 26.35,60.34 27.65,61.64 IC6.2
N$44
  Top 0.406: IC7.3 30.19,80.15 C13.-
N$45
  Top 0.406: IC7.1 23.46,82.04 C13.+
N$46
  Top 0.406: IC7.4 32.73,78.78 C14.+
N$47
  Top 0.406: IC7.5 37.54,81.42 C14.-
N$48
  Top 0.406: C16.- 37.81,83.15 IC7.6
N$49
  Bottom 0.406: C15.+ 22.96,81.93 26.35,81.93 27.65,83.23 IC7.2
N$50
  Top 0.406: IC2.16 85.23,40.74 83.82,39.33 60.02,39.33 IC1.16
  Bottom 0.406: QG1.8 98.45,19.21 98.45,27.44 85.34,40.55 IC2.16
RTS0
  Bottom 0.406: IC3.7 40.35,20.32 39.01,21.65 29.87,21.65 28.96,22.57 28.96,24.7 28.04,25.62 5.75,25.62 X4.7
RTS1
  Bottom 0.406: IC6.7 40.35,66.34 38.71,67.98 29.57,67.98 28.96,68.59 28.96,70.73 28.04,71.64 X5.7 | X5.7
RX0
  Top 0.406: IC3.8 42.89,20.83 42.06,21.65 24.99,21.65 21.64,25.01 9.01,25.01 X4.2
RX1
  Top 0.406: IC6.8 42.89,67.16 42.06,67.98 24.69,67.98 21.03,71.64 9.64,71.64 X5.2
TX0
  Bottom 0.406: IC3.14 30.19,25.6 28.65,27.14 8.4,27.14 X4.3
TX1
  Bottom 0.406: IC6.14 30.19,71.63 28.65,73.16 8.42,73.16 X5.3

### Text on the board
_tsilk: 1 | IC11 | RN1 | MAX232 | 74LS245N | IC7 | IC1 | IC2 | 16C550 | 16C550 | MAX232 | IC6 | UART1 | 74LS04N | IC5 | 74LS08N | MAX232 | IC10 | IC4 | IC8 | IC9 | 74LS138N | 74LS02N | QG1 | MAX232 | IC3 | 1.8432MHz | UART0 | 1 | UART v1.0.2, (C) D.Pilawa, 10.2011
